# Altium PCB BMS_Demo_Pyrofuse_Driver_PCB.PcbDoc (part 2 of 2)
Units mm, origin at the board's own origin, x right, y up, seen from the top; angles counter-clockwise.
Board outline 130 x 44 mm, 2 copper layers (Top Layer, Bottom Layer), stack 1.575 mm thick; 66 components, 31 nets, 200 pads, 139 vias.
Unrouted connection lines stored in the file: 5.
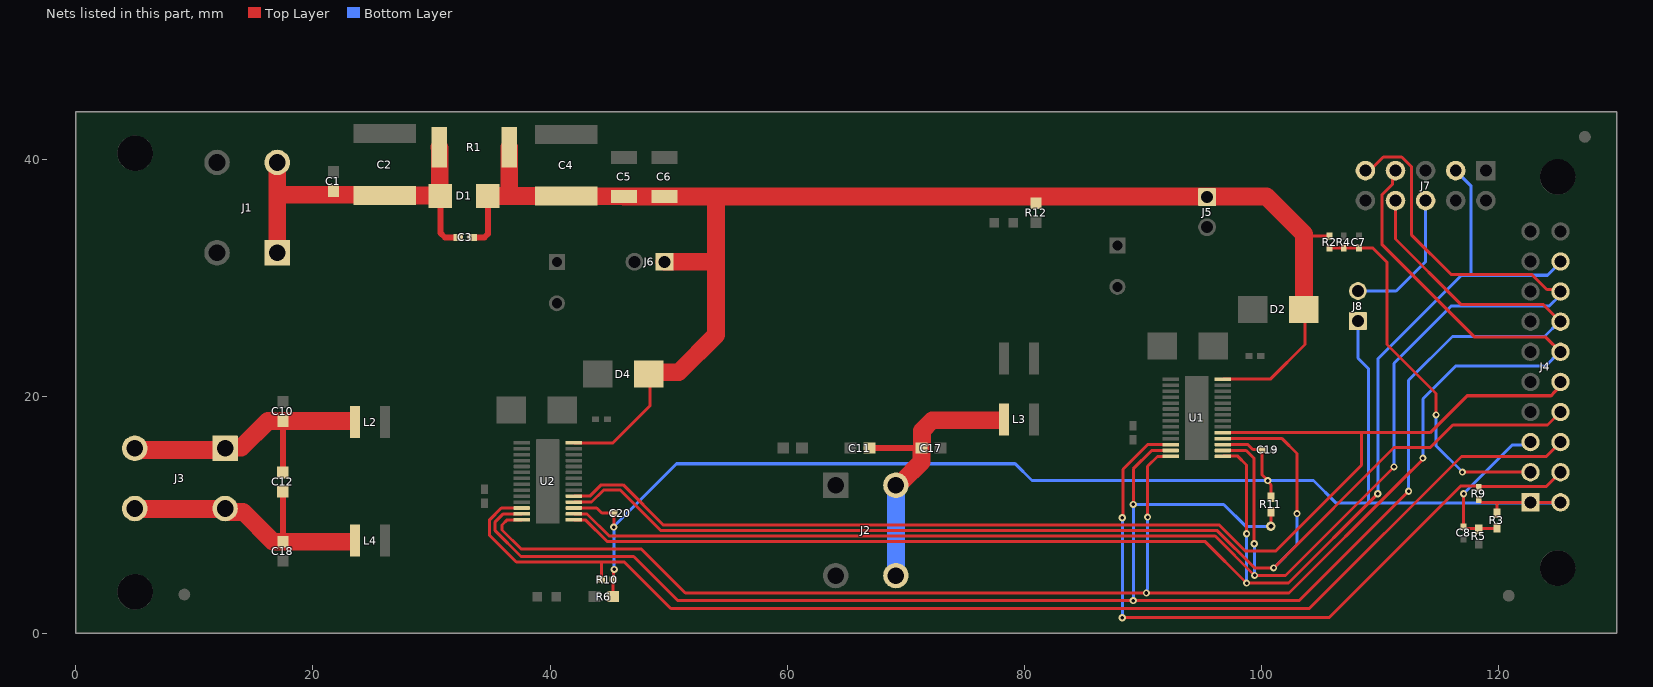
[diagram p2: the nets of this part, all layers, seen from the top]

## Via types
v1: diameter 0.8, hole 0.4, Top Layer to Bottom Layer, 71 vias
v2: diameter 0.61, hole 0.3, Top Layer to Bottom Layer, 40 vias
v3: diameter 0.5, hole 0.2, Top Layer to Bottom Layer, tented both sides, 28 vias

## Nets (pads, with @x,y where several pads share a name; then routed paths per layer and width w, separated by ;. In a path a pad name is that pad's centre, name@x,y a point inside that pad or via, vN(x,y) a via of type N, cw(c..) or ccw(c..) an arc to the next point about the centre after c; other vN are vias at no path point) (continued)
Pyro1-: C11.2 C17.1 J2.2 L3.2 | length 24.9
  Top Layer w0.5: C11.2@67.021,15.628 C17.1@71.346,15.628
  Top Layer w1.5: J2.2@68.96,12.24 68.96,12.273 J2.2@69.177,12.49 69.427,12.74 69.635,12.74 71.346,14.451 C17.1@71.346,15.628 71.371,15.653 71.371,17.098 72.249,17.977 L3.2@77.963,17.977
  Bottom Layer w1.5: J2.2@69.177,4.87 J2.2@69.177,12.49
Pyro2+: C10.1 C12.1 J3.1 L2.2 | length 23.6
  Top Layer w0.5: C12.1@17.462,13.575 C10.1@17.462,17.825 ; C10.1@17.462,17.825 C10.1@17.463,17.917
  Top Layer w1.5: J3.1@4.994,15.479 5.529,15.479 5.54,15.469 12.458,15.469 12.565,15.575 12.835,15.575 12.931,15.671 13.951,15.671 16.198,17.917 C10.1@17.463,17.917 17.766,17.917 17.775,17.909 L2.2@23.213,17.909
Pyro2-: C12.2 C18.1 J3.2 L4.2 | length 23.8
  Top Layer w0.5: C18.1@17.462,7.726 17.462,7.825 C12.2@17.462,11.974
  Top Layer w1.5: J3.2@4.856,10.495 12.7,10.495 12.95,10.245 14.109,10.245 16.629,7.725 C18.1@17.463,7.725 17.47,7.718 L4.2@23.213,7.718
PYRO_IO0: J4.4 R9.1 U1.26 | length 59.5
  Top Layer w0.254: v2(88.275,1.321) 105.714,1.321 116.804,12.411 118.34,12.411 118.351,12.4 124.06,12.4 J4.4@125.25,13.59 ; v2(88.275,9.757) 88.334,9.816 88.334,13.839 90.42,15.925 U1.26@92.363,15.925
  Bottom Layer w0.254: v2(88.275,1.321) v2(88.275,9.757)
PYRO_IO1: J4.6 R10.1 U2.26 | length 104.7
  Top Layer w0.254: U2.26@37.613,10.575 37.609,10.571 35.894,10.571 34.873,9.55 34.873,8.299 37.151,6.021 44.33,6.021 ; R10.1@44.33,4.529 44.33,6.021 ; J4.6@125.25,16.13 124.045,14.925 116.885,14.925 104.06,2.1 50.192,2.1 46.271,6.021 44.33,6.021
PYRO_IO2: J4.8 U1.4 U2.4 | length 109.1
  Top Layer w0.254: U2.4@42.013,11.075 43.501,11.075 44.501,12.075 45.95,12.075 49.36,8.665 96.299,8.665 99.447,5.518 v2(101.043,5.518) 111.201,15.675 114.267,15.675 116.16,17.568 124.148,17.568 J4.8@125.25,18.67 ; U1.4@96.763,16.425 101.768,16.425 103.016,15.177 v2(103.016,10.099)
  Bottom Layer w0.254: v2(101.043,5.518) 103.016,7.49 v2(103.016,10.099)
PYRO_IO3: J4.10 U1.5 U2.5 | length 105.4
  Top Layer w0.254: U2.5@42.013,11.575 43.359,11.575 44.313,12.529 46.168,12.529 49.578,9.119 96.487,9.119 98.677,6.929 101.199,6.929 108.453,14.184 108.453,16.925 ; U1.5@96.763,16.925 108.453,16.925 ; J4.10@125.25,21.21 125.25,20.859 124.643,20.252 124.643,20.226 124.46,20.043 117.369,20.043 114.252,16.925 108.453,16.925
PYRO_OPT_AN0: C7.1 J4.3 R2.1 R4.2 | length 31.4
  Top Layer w0.254: R2.1@105.768,32.495 R4.2@106.962,32.495 C7.1@108.232,32.495 109.433,32.495 110.617,31.31 110.617,24.359 114.749,20.226 v2(114.749,18.425) ; v2(116.972,13.602) 116.978,13.596 122.704,13.596 J4.3@122.71,13.59
  Bottom Layer w0.254: v2(114.749,18.425) 114.749,15.825 v2(116.972,13.602)
PYRO_OPT_AN1: C8.1 J4.5 R3.1 R5.2 | length 12.9
  Top Layer w0.254: v2(117.066,11.779) C8.1@117.066,8.974 117.182,8.858 118.267,8.858 R5.2@118.351,8.774 ; R5.2@118.351,8.847 R3.1@119.676,8.847
  Bottom Layer w0.254: v2(117.066,11.779) 121.169,15.882 122.462,15.882 J4.5@122.71,16.13
PYRO_SPI_CS: J4.16 J7.9 U1.2 U2.2 | length 138.4
  Top Layer w0.254: U2.2@42.013,10.075 43.122,10.075 44.986,8.211 96.111,8.211 v2(99.437,4.886) 102.047,4.886 v2(111.201,14.04) ; U1.2@96.763,15.425 98.725,15.425 99.407,14.742 v2(99.407,7.561) ; J7.9@108.788,39.04 109.144,39.04 110.296,40.192 111.844,40.192 112.657,39.379 112.657,33.632 116.021,30.268 122.83,30.268 124.094,29.004 125.076,29.004 J4.16@125.25,28.83
  Bottom Layer w0.254: v2(99.407,7.561) 99.422,7.546 99.422,4.9 v2(99.437,4.886) ; v2(111.201,14.04) 111.201,22.783 116.026,27.608 124.307,27.608 125.25,28.551 J4.16@125.25,28.83
PYRO_SPI_MISO: J4.14 J7.8 R11.1 U1.27 U2.27 | length 159.4
  Top Layer w0.254: U2.27@37.613,10.075 37.59,10.052 36.017,10.052 35.375,9.41 35.375,8.659 37.559,6.475 47.054,6.475 50.765,2.764 103.212,2.764 v2(112.431,11.984) ; v2(89.205,10.876) 89.205,13.873 90.756,15.425 U1.27@92.363,15.425 ; v1(100.813,9.024) R11.1@100.813,10.276 ; J7.8@111.328,36.5 111.328,33.274 116.874,27.728 123.812,27.728 J4.14@125.25,26.29
  Bottom Layer w0.254: v2(89.205,2.764) v2(89.205,10.876) 96.83,10.876 98.682,9.024 v1(100.813,9.024) ; v2(112.431,11.984) 112.431,21.341 116.135,25.044 123.887,25.044 125.133,26.29 J4.14@125.25,26.29
PYRO_SPI_MOSI: J4.12 J7.7 U1.28 U2.28 | length 143.7
  Top Layer w0.254: U2.28@37.613,9.575 36.382,9.575 35.95,9.143 35.95,8.726 37.567,7.108 47.703,7.108 51.411,3.4 v2(90.313,3.4) 102.348,3.4 111.809,12.861 113.638,14.69 v2(113.638,14.783) ; v2(90.413,9.803) 90.413,14.09 91.249,14.925 U1.28@92.363,14.925 ; J7.7@111.328,39.04 111.061,38.773 111.061,37.862 110.176,36.977 110.176,32.817 118.005,24.989 124.011,24.989 J4.12@125.25,23.75
  Bottom Layer w0.254: v2(90.313,3.4) 90.381,3.468 90.381,3.695 90.413,3.727 v2(90.413,9.803) ; v2(113.638,14.783) 113.638,19.788 116.39,22.539 123.981,22.539 125.191,23.75 J4.12@125.25,23.75
PYRO_SPI_SCK: J4.18 J7.3 U1.1 U2.1 | length 125
  Top Layer w0.254: U2.1@42.013,9.575 42.98,9.575 44.798,7.757 95.244,7.757 v2(98.762,4.238) 102.293,4.238 v2(109.834,11.779) ; U1.1@96.763,14.925 96.786,14.947 98.021,14.947 98.762,14.206 v2(98.762,8.392)
  Bottom Layer w0.254: v2(98.762,4.238) v2(98.762,8.392) ; v2(109.834,11.779) 109.834,23.143 116.899,30.208 117.678,30.208 ; J7.3@116.408,39.04 117.678,37.77 117.678,30.208 ; J4.18@125.25,31.37 125.25,31.31 124.148,30.208 117.678,30.208
VBAT: C3.1 C4.1 C5.1 C6.1 D1.1 D2.2 D4.2 J5.1 J6.1 R1.2 R2.2 R12.2 U1.14 U2.14 | length 132.1
  Top Layer w0.254: U2.14@42.013,16.075 45.316,16.075 48.453,19.212 D4.2@48.453,21.718 ; D4.2@47.443,21.874 D4.2@47.766,21.551 ; U1.14@96.763,21.425 96.782,21.444 100.769,21.444 103.694,24.37 103.694,27.22 D2.2@103.593,27.321 ; 103.728,33.92 104.137,33.511 R2.2@105.768,33.511
  Top Layer w0.5: C3.1@33.45,33.4 34.457,33.4 34.75,33.693 D1.1@34.75,36.9
  Top Layer w1.5: D1.1@34.75,36.9 36.619,36.9 ; R1.2@36.55,41.005 36.55,36.969 36.619,36.9 ; C5.1@46.25,36.85 C6.1@49.65,36.85 54,36.85 ; C5.1@46.25,36.875 41.388,36.875 C4.1@41.363,36.9 36.619,36.9 ; D4.2@48.574,22.031 50.863,22.031 54,25.167 54,31.344 ; J6.1@49.657,31.344 54,31.344 ; D2.2@103.593,27.321 103.609,27.336 103.609,33.683 100.442,36.85 95.428,36.85 83.713,36.85 70.719,36.85 54,36.85 ; 54,31.344 54,36.85
VBATI: C1.1 C2.1 C3.2 D1.2 J1.1 R1.1 | length 30.3
  Top Layer w0.5: D1.2@30.75,36.9 30.75,33.787 31.137,33.4 C3.2@32.25,33.4
  Top Layer w1.5: J1.1@16.987,31.893 16.987,37 ; J1.1@16.987,39.513 16.987,37 ; R1.1@30.65,41.005 30.7,40.955 30.7,36.95 D1.2@30.725,36.925 ; D1.2@30.75,36.9 D1.2@30.725,36.925 ; 16.987,37 26,37 C2.1@26.05,36.95 26.075,36.925 D1.2@30.725,36.925
VDD_USB2ANY: J7.6 J8.2 | length 11.9
  Bottom Layer w0.254: J8.2@108.153,28.878 111.378,28.878 113.868,31.369 J7.6@113.868,36.5
VDDIO: C19.2 C20.2 J4.1 J4.2 J8.1 R3.2 R6.2 R9.2 R10.2 R11.2 U1.3 U2.3 | length 125.7
  Top Layer w0.254: U2.3@42.013,10.575 43.935,10.575 44.363,10.146 C20.2@45.41,10.146 45.392,10.128 45.392,8.982 v2(45.374,8.964) ; R6.2@45.339,3.099 45.33,3.107 R10.2@45.33,4.529 45.37,4.569 45.37,5.349 v2(45.411,5.389) ; U1.3@96.763,15.925 98.867,15.925 99.293,15.499 C19.2@100.013,15.499 ; C19.2@100.043,15.481 100.051,15.473 100.051,13.392 v2(100.558,12.885) 100.558,12.789 100.813,12.534 R11.2@100.813,11.476 R11.2@100.813,11.426 ; R9.2@118.351,11.279 118.351,11.229 118.474,11.106 118.524,11.106 118.58,11.05 119.888,11.05 ; R3.2@119.888,10.125 119.888,11.05 ; J4.2@125.25,11.05 J4.1@122.71,11.05 119.888,11.05
  Bottom Layer w0.254: v2(45.411,5.389) 45.392,5.407 45.392,8.946 v2(45.374,8.964) 45.374,9.008 50.673,14.306 79.242,14.306 80.663,12.885 v2(100.558,12.885) 104.408,12.885 106.318,10.975 109.03,10.975 ; J8.1@108.153,26.338 108.153,23.212 109.03,22.335 109.03,10.975 ; J4.2@125.25,11.05 125.175,10.975 109.03,10.975
pads on no net: FID1.1 FID2.1 FID3.1 J4.7 J4.9 J4.11 J4.13 J4.15 J4.17 J7.1 J7.2 J7.4 J7.10 LBL1.0

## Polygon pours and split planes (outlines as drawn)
NetL1_1 on Top Layer "BOTTOM_LAYER_NONET_P-001" (solid, pour order 9): 93.013,20.049 93.013,19.3 88.334,19.3 83.222,21.825 80.838,21.825 80.838,24.525 85.553,24.525 90.029,20.049
NetL3_1 on Top Layer "BOTTOM_LAYER_NONET_P-001" (solid, pour order 10): 93.015,19.068 93.015,18.313 88.357,18.313 87.048,16.678 80.84,16.707 80.84,19.39 84.216,19.396 87.627,19.038
GND on Top Layer "BOTTOM_LAYER_NONET_P-001" (solid, remove dead copper, pour order 16): 0,44 0,0 130,0 130,44
NetL3_1 on Top Layer "BOTTOM_LAYER_NONET_P-001" (solid, pour order 15): 99.814,19.051 99.814,18.292 96.215,18.285 96.215,19.045
NetL1_1 on Top Layer "BOTTOM_LAYER_NONET_P-001" (solid, pour order 14): 99.417,20.043 99.417,19.301 96.206,19.295 96.206,20.038
NetC15_1 on Top Layer "BOTTOM_LAYER_NONET_P-001" (solid, pour order 13): 99.043,21.049 99.043,20.307 96.263,20.302 96.263,21.045
NetC13_1 on Top Layer "BOTTOM_LAYER_NONET_P-001" (solid, pour order 12): 90.414,31.421 86.413,31.421 86.413,34.265 92.888,34.265 92.888,21.276 90.414,21.276
NetC15_1 on Top Layer "BOTTOM_LAYER_NONET_P-001" (solid, pour order 11): 93.025,21.068 93.025,20.279 90.143,20.274 90.143,21.063
VBAT on Top Layer "BOTTOM_LAYER_NONET_P-001" (solid, pour order 8): 96.113,21.288 96.113,22.707 101.268,22.707 103.05,24.489 103.05,26.821 104.597,26.821 104.597,23.79 102.096,21.288
VBAT on Top Layer "BOTTOM_LAYER_NONET_P-001" (solid, pour order 7): 41.363,15.952 41.363,17.26 45.555,17.26 47.766,19.471 47.766,21.529 49.225,21.529 49.225,18.988 46.189,15.952
NetL4_1 on Top Layer "BOTTOM_LAYER_NONET_P-001" (solid, pour order 6): 45.18,13.707 45.18,12.948 41.372,12.941 41.372,13.701
NetL2_1 on Top Layer "BOTTOM_LAYER_NONET_P-001" (solid, pour order 5): 44.538,14.699 44.538,13.957 41.363,13.951 41.363,14.694
NetC16_1 on Top Layer "BOTTOM_LAYER_NONET_P-001" (solid, pour order 4): 44.128,15.705 44.128,14.963 41.421,14.958 41.421,15.701
NetC14_1 on Top Layer "BOTTOM_LAYER_NONET_P-001" (solid, pour order 3): 35.545,32.845 41.863,32.845 41.863,29.814 37.861,29.814 37.861,15.922 35.545,15.922
NetC16_1 on Top Layer "BOTTOM_LAYER_NONET_P-001" (solid, pour order 2): 38.252,15.705 38.252,14.916 35.545,14.912 35.545,15.701
NetL4_1 on Top Layer "BOTTOM_LAYER_NONET_P-001" (solid, pour order 1): 38.263,13.725 38.263,12.94 33.863,12.94 33.128,9.773 30.095,6.475 26.091,6.475 26.091,9.175 28.968,9.175 32.3,12.507 33.519,13.726
NetL2_1 on Top Layer "BOTTOM_LAYER_NONET_P-001" (solid, pour order 0): 38.263,14.705 38.263,13.942 33.52,13.942 28.518,16.475 26.088,16.475 26.088,19.175 30.654,19.175 35.124,14.705
GND on Bottom Layer "BOTTOM_LAYER_NONET_P-001" (solid, remove dead copper, pour order 17): 0,44 0,0 130,0 130,44

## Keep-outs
Keep-Out Layer:
  text ".Layer_Name" at 14.656,-21.806 h1.52

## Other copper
Top Layer:
  text ".Layer_Name" at 14.656,-21.806 h1.52
Bottom Layer:
  text ".Layer_Name" at 14.656,-21.806 h1.52

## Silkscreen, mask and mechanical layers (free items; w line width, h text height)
Top Overlay:
  text "'.PRJ_Number'.PCB_Rev" at 86.104,41.148 h2.75
  text "TI BMS DEMO - PYROFUSE DRIVER" at 51.98,38.408 h1.52
  text "USB2ANY" at 114.749,34.617 h1
  text "VBAT" at 76.889,32.831 h1
  text "GND" at 4.039,32.605 h1.52
  text "VBATI" at 20.692,32.315 h1.52
  text "Pyro2+" at 10.737,20.031 h1.52
  text "Pyrofuse Driver-DRV3901-Q1" at 81.813,12.631 h1.52
  text "Pyro1+" at 54.987,8.111 h1.52
  text "Pyro1-" at 74.643,8.043 h1.52
  text "Pyrofuse Driver-DRV3901-Q1" at 30.937,6.281 h1.52
  text "Pyro2-" at 10.737,4.519 h1.52
  text "VDDIO" at 38.169,1.048 h1
  text ".Layer_Name" at 14.656,-21.806 h1.52
Bottom Overlay:
  text ".Layer_Name" at 14.656,-21.806 h1.52
Top Paste:
  text ".Layer_Name" at 14.656,-21.806 h1.52
Bottom Paste:
  text ".Layer_Name" at 14.656,-21.806 h1.52
Top Solder:
  text ".Layer_Name" at 14.656,-21.806 h1.52
  text ".Layer_Name" at 14.656,-21.806 h1.52
Bottom Solder:
  text ".Layer_Name" at 14.656,-21.806 h1.52
Drill Guide:
  text ".Layer_Name" at 14.656,-21.806 h1.52
M1 Board Outline:
  the board outline again, w0.254
  text ".Layer_Name" at 14.656,-21.806 h1.52
M2 Board Dimensions:
  rectangle: 3.175,-10.16 12.7,-6.985
  rectangle: 0,-6.985 3.175,-3.81
  lines w0.178: 0,-6.985 25.4,-6.985 ; 3.175,-10.16 3.175,-3.81 ; 6.35,-10.16 6.35,-3.81 ; 12.7,-10.16 12.7,-3.81 ; 19.05,-10.16 19.05,-3.81 ; 0,-10.16 0,-3.81 25.4,-3.81 25.4,-10.16 0,-10.16
  text ".Layer_Name" at 14.656,-21.806 h1.52
M3 3D STEP Top:
  text ".Layer_Name" at 14.656,-21.806 h1.52
M4 3D STEP Bottom:
  text ".Layer_Name" at 14.656,-21.806 h1.52
M5 Assembly Top:
  lines w0.254: -7.417,-23.626 160.223,-23.626 ; -7.417,-18.462 160.274,-18.462 ; -7.417,-13.297 -7.417,-28.791 94.31,-28.791 160.274,-28.791 160.274,-13.297 -7.404,-13.297 -7.404,-28.791 32.614,-28.791 ; 55.194,-28.791 55.194,-13.297 ; 87.376,-18.462 87.376,-13.297 ; 108.712,-18.462 108.712,-13.297 ; 124.511,-28.956 124.511,-23.804
  text "COMPONENTS MARKED 'DNP' SHOULD NOT BE POPULATED." at 29.299,-8.09 h1.52
  text "ASSEMBLY VARIANT:" at 29.286,-11.024 h1.52
  text ".VariantName" at 55.601,-11.024 h1.52
  text "PCB VIEWED FROM TOP SIDE" at -5.804,-16.654 h1.52
  text "BOARD #:" at 57.099,-16.654 h1.52
  text ".PRJ_Number" at 70.955,-16.654 h1.52
  text "REV:" at 92.405,-16.654 h1.52
  text ".PCB_Rev" at 99.809,-16.654 h1.52
  text "SVN REV:" at 113.69,-16.654 h1.52
  text ".VersionControl_RevNumber" at 126.543,-16.654 h1.52
  text "PLOT NAME =" at -5.804,-27.034 h1.52
  text ".plot_File_Name" at 14.656,-27.034 h1.52
  text "GENERATED    :" at 57.15,-27.034 h1.52
  text ".Print_Date" at 79.235,-27.034 h1.52
  text ".Print_Time" at 97.752,-27.034 h1.52
  text "TEXAS INSTRUMENTS" at 129.87,-27.034 h1.52
M6 Assembly Bottom:
  lines w0.254: -7.429,-18.474 160.261,-18.474 ; -7.379,-23.639 160.261,-23.639 ; 28.334,-28.969 28.334,-23.817 ; 44.133,-18.474 44.133,-13.31 ; 65.468,-18.474 65.468,-13.31 ; 97.65,-28.804 97.65,-13.31 ; 120.231,-28.804 160.249,-28.804 160.249,-13.31 -7.429,-13.31 -7.429,-28.804 58.534,-28.804 160.261,-28.804 160.261,-13.31
  text "COMPONENTS MARKED 'DNP' SHOULD NOT BE POPULATED." at 154.991,-8.077 h1.52
  text ".VariantName" at 128.473,-11.024 h1.52
  text "ASSEMBLY VARIANT:" at 154.864,-11.024 h1.52
  text ".VersionControl_RevNumber" at 26.302,-16.667 h1.52
  text "SVN REV:" at 39.154,-16.667 h1.52
  text ".PCB_Rev" at 53.035,-16.667 h1.52
  text "REV:" at 60.439,-16.667 h1.52
  text ".PRJ_Number" at 81.89,-16.667 h1.52
  text "BOARD #:" at 95.745,-16.667 h1.52
  text "PCB VIEWED FROM BOTTOM SIDE" at 158.648,-16.667 h1.52
  text "TEXAS INSTRUMENTS" at 22.974,-27.047 h1.52
  text ".Print_Time" at 55.093,-27.047 h1.52
  text ".Print_Date" at 73.609,-27.047 h1.52
  text "GENERATED    :" at 95.694,-27.047 h1.52
  text ".plot_File_Name" at 138.189,-27.047 h1.52
  text "PLOT NAME =" at 158.648,-27.047 h1.52
M9 Title Sheet:
  drawing of 56 lines, arcs and shapes, not listed
  text "1" at 26.882,339.887 h1.78
  text "2" at 111.354,339.887 h1.78
  text "3" at 195.936,339.887 h1.78
  text "4" at 280.645,339.887 h1.78
  text "5" at 365.1,339.887 h1.78
  text "6" at 449.809,339.887 h1.78
  text "A" at -11.76,294.726 h1.78
  text "A" at 488.62,294.726 h1.78
  text "B" at -11.76,199.476 h1.78
  text "B" at 488.62,199.476 h1.78
  text "C" at -11.76,104.226 h1.78
  text "C" at 488.62,104.226 h1.78
  text "D" at -11.76,8.976 h1.78
  text "D" at 488.62,8.976 h1.78
  text "PROJECT TITLE:" at 410.032,6.817 h1.14
  text ".PRJ_Title" at 411.302,3.431 h1.78
  text "DESIGNED FOR:" at 410.032,-0.828 h1.14
  text ".PRJ_Customer" at 411.302,-4.384 h1.78
  text "FILE NAME:" at 410.032,-8.448 h1.14
  text ".PCB_File_Name_No_Path" at 411.302,-11.496 h1.78
  text "Texas Instruments (TI) and/or its licensors do not warrant the accuracy or completeness of this specification" at 283.807,-15.607 h1.14
  text "ENGINEER:" at 410.032,-15.814 h1.14
  text "LAYOUT BY:" at 448.259,-15.814 h1.14
  text "or any information contained therein. TI and/or its licensors do not warrant that this design will meet" at 282.664,-18.469 h1.14
  text ".PRJ_Engineer" at 411.302,-19.751 h1.78
  text ".PCB_Layout" at 449.542,-19.751 h1.78
  text "the specifications, will be suitable for your application or fit for any particular purpose, or will operate in" at 282.664,-21.33 h1.14
  text ".Layer_Name" at 14.656,-21.806 h1.52
  text "ALTIUM DESIGNER VERSION:" at 448.259,-23.688 h1.14
  text "an implementation. TI and/or its licensors do not warrant that the design is production worthy. You should" at 282.664,-24.192 h1.14
  text "completely validate and test your design implementation to confirm the system functionality for your application." at 283.807,-27.054 h1.14
  text ".print_Scale" at 411.302,-27.075 h1.78
  text ".Application_BuildNumber" at 449.542,-27.075 h1.78
  text "1" at 26.882,-33.493 h1.78
  text "2" at 111.354,-33.493 h1.78
  text "3" at 195.936,-33.493 h1.78
  text "4" at 280.645,-33.493 h1.78
  text "5" at 365.1,-33.493 h1.78
  text "6" at 449.809,-33.493 h1.78
M10 Fab Notes:
  drawing of 189 lines, arcs and shapes, not listed
  text "DESIGN INFORMATION" at 436.322,161.675 h1.52
  text "MIN. TRACK WIDTH:" at 419.95,158.319 h1.52
  text "8" at 447.794,158.32 h1.52
  text "MIL" at 451.725,158.319 h1.52
  text "MIN. CLEARANCE:" at 419.95,155.167 h1.52
  text "MIL" at 451.725,155.167 h1.52
  text "7.874" at 443.475,155.05 h1.52
  text "MIN. VIA PAD SIZE:" at 419.95,152.014 h1.52
  text "24" at 447.033,152.014 h1.52
  text "MIL" at 451.725,152.014 h1.52
  text "0.05mm (2MIL)" at 437.603,148.714 h1.52
  text "MINIMUM ANNULAR RING" at 411.587,148.506 h1.52
  text "EXTERNAL" at 455.586,148.506 h1.52
  text "PER" at 416.667,145.708 h1.52
  text "IPC-D-275 CLASS 2 LEVEL C" at 422.255,145.708 h1.52
  text "MIL, HOLES" at 460.056,143.156 h1.52
  text "+/-" at 450.088,142.938 h1.52
  text "+/-" at 471.78,142.938 h1.52
  text "REGISTRATION TOLERANCES:" at 411.587,142.911 h1.52
  text "METAL" at 442.062,142.911 h1.52
  text "5" at 456.697,142.911 h1.52
  text "3" at 477.855,142.911 h1.52
  text "MIL" at 480.808,142.911 h1.52
  text "HOLE SIZE TOLERANCE (UNLESS OTHERWISE SPECIFIED):" at 411.587,140.414 h1.52
  text "+/-" at 471.78,140.341 h1.52
  text "3" at 477.855,140.314 h1.52
  text "MIL" at 480.808,140.314 h1.52
  text "MATERIAL:" at 409.688,136.818 h1.52
  text "FR-4 High Tg" at 434.744,133.553 h1.52
  text "X" at 431.075,133.35 h1.52
  text "FR-408" at 420.382,133.235 h1.52
  text "OTHER" at 458.177,133.235 h1.52
  text "62 MIL (1.6mm) +/-10%" at 428.512,129.602 h1.52
  text "X" at 425.462,129.54 h1.52
  text "THICKNESS:" at 411.587,129.394 h1.52
  text "OTHER" at 461.149,129.394 h1.52
  text "TOLERANCE:" at 411.587,125.88 h1.52
  text "X" at 433.133,125.88 h1.52
  text "ANSI IPC-6012 TYPE 3 CLASS 2" at 437.654,125.88 h1.52
  text "OTHER +/-" at 437.654,122.218 h1.52
  text "BOW & TWIST:" at 411.587,118.53 h1.52
  text "X" at 433.133,118.53 h1.52
  text "ANSI IPC-6012 TYPE 3 CLASS 2" at 437.654,118.53 h1.52
  text "OTHER +/-" at 437.654,114.804 h1.52
  text "DRILLING:" at 409.688,111.486 h1.52
  text "NC_DRILL FILES" at 454.418,108.815 h1.52
  text "REFERENCE:" at 411.587,108.715 h1.52
  text "X" at 428.281,108.712 h1.52
  text "AS SHOWN" at 432.802,108.715 h1.52
  text "X" at 451.167,108.715 h1.52
  text "OTHER" at 461.987,105.101 h1.52
  text "PTH COPPER THICKNESS:" at 411.579,105.012 h1.52
  text "X" at 440.516,105.012 h1.52
  text "20-30 um" at 443.767,105.012 h1.52
  text "BOARD FINISH:" at 409.688,101.263 h1.52
  text "SILKSCREEN:" at 413.631,98.466 h1.52
  text "X" at 437.959,98.466 h1.52
  text "TOP" at 440.93,98.466 h1.52
  text "X" at 450.913,98.466 h1.52
  text "BOTTOM" at 453.91,98.466 h1.52
  text "SILKSCREEN COLOR:" at 413.631,94.524 h1.52
  text "X" at 437.933,94.524 h1.52
  text "WHITE" at 440.93,94.524 h1.52
  text "OTHER" at 453.91,94.524 h1.52
  text "X" at 441.261,90.88 h1.52
  text "GREEN" at 444.258,90.88 h1.52
  text "OTHER" at 459.955,90.88 h1.52
  text "SOLDER RESIST COLOR:" at 413.631,90.706 h1.52
  text "X" at 441.261,86.962 h1.52
  text "MATTE" at 444.258,86.962 h1.52
  text "SEMI-GLOSS" at 459.943,86.946 h1.52
  text "IMMERSION GOLD (ENIG)" at 436.638,82.574 h1.52
  text "ENEPIG" at 470.611,82.39 h1.52
  text "SURFACE FINISH:" at 409.688,82.365 h1.52
  text "X" at 432.117,82.365 h1.52
  text "IMM. TIN/SILVER OR EQUIV" at 418.059,78.877 h1.52
  text "OTHER" at 454.418,78.777 h1.52
  text "ARRAY/PANEL:" at 409.688,74.831 h1.52
  text "CUT AND TRIM PER M1 BOARD OUTLINE" at 436.638,74.622 h1.52
  text "N.C. ROUTE" at 436.638,71.168 h1.52
  text "X" at 454.113,71.168 h1.52
  text "V. SCORE" at 458.634,71.168 h1.52
  text "CERTIFICATION:" at 409.688,67.888 h1.52
  text "MATERIALS AND WORKMANSHIP FOR ALL PCBS" at 428.103,67.888 h1.52
  text "TO MEET OR EXCEED THE REQUIREMENTS OF:" at 428.103,65.499 h1.52
  text "X" at 418.896,62.232 h1.52
  text "ANSI IPC-A-600F CLASS ->" at 422.147,62.232 h1.52
  text "X" at 464.006,62.232 h1.52
  text "2" at 466.8,62.232 h1.52
  text "1" at 458.799,62.194 h1.52
  text "3" at 475.792,62.194 h1.52
  text "X" at 439.521,58.481 h1.52
  text "RoHS" at 442.772,58.481 h1.52
  text "OTHER" at 459.14,58.481 h1.52
  text "PER ORDER" at 469.225,58.481 h1.52
  text "ALL BOARDS MUST MEET OR EXCEED UL94-V0 REQUIREMENTS." at 410.388,54.574 h1.52
  text "PCB MUST BEAR THE UL94V-0 UL REGISTERED MATERIAL ID NUMBER" at 410.388,51.626 h1.52
  text "ADDITIONAL REQUIREMENTS:" at 409.688,47.322 h1.52
  text "MICROSECTION:" at 411.587,44.601 h1.52
  text "YES" at 434.593,44.601 h1.52
  text "REQUIRED" at 456.475,40.935 h1.52
  text "BARE BOARD ELEC. TEST:" at 411.587,40.863 h1.52
  text "NONE" at 444.753,40.863 h1.52
  text "X" at 453.478,40.863 h1.52
  text "PER ORDER" at 471.512,40.863 h1.52
  text "XX MIL VIAS REQUIRE NON-CONDUCTIVE FILL AND PLANARIZE" at 415.858,35.657 h1.5
  text "XX MIL VIAS REQUIRE CONDUCTIVE FILL AND PLANARIZE" at 416.062,33.016 h1.52
  text "OUTER XX MIL TRACES REQUIRE 50 OHM SINGLE-ENDED IMPEDANCE" at 416.037,28.866 h1.47
  text "LAYER 2 & 3 (INNER LAYERS) XX MIL WIDE, XX MIL SPACE / TRACES REQUIRE 100 OHM DIFFERENTIAL IMPEDANCE" at 415.833,22.879 h1.52
  text ".Layer_Name" at 14.656,-21.806 h1.52
M11 Gerber Information:
  lines w0.254: -7.417,-23.626 160.223,-23.626 ; -7.417,-18.462 160.274,-18.462 ; -7.417,-13.297 -7.417,-28.791 94.31,-28.791 160.274,-28.791 160.274,-13.297 -7.404,-13.297 -7.404,-28.791 32.614,-28.791 ; 55.194,-28.791 55.194,-13.297 ; 87.376,-18.462 87.376,-13.297 ; 108.712,-18.462 108.712,-13.297 ; 124.511,-28.956 124.511,-23.804
  text "ALL ARTWORK VIEWED FROM TOP SIDE" at -5.804,-16.654 h1.52
  text "BOARD #:" at 57.099,-16.654 h1.52
  text ".PRJ_Number" at 70.955,-16.654 h1.52
  text "REV:" at 92.405,-16.654 h1.52
  text ".PCB_Rev" at 99.809,-16.654 h1.52
  text "SVN REV:" at 113.69,-16.654 h1.52
  text ".VersionControl_RevNumber" at 126.543,-16.654 h1.52
  text "LAYER NAME =" at -5.804,-21.806 h1.52
  text "PLOT NAME =" at -5.804,-27.034 h1.52
  text ".plot_File_Name" at 14.656,-27.034 h1.52
  text "GENERATED    :" at 57.15,-27.034 h1.52
  text ".Print_Date" at 79.235,-27.034 h1.52
  text ".Print_Time" at 97.752,-27.034 h1.52
  text "TEXAS INSTRUMENTS" at 129.87,-27.034 h1.52
M12 Stackup:
  drawing of 191 lines, arcs and shapes, not listed
  text "Layer" at 370.969,332.524 h1.52
  text "Name" at 381.38,332.524 h1.52
  text "Material" at 404.996,332.524 h1.52
  text "Thickness" at 426.834,332.524 h1.52
  text "Constant" at 443.34,332.524 h1.52
  text "Board Layer Stack" at 457.814,332.524 h1.52
  text "Top Overlay" at 381.38,329.476 h1.52
  text "Top Solder" at 381.38,326.428 h1.52
  text "Solder Resist" at 404.996,326.428 h1.52
  text "0.40mil" at 426.834,326.428 h1.52
  text "3.5" at 443.34,326.428 h1.52
  text "1" at 370.969,323.38 h1.52
  text "Top Layer" at 381.38,323.38 h1.52
  text "1.40mil" at 426.834,323.38 h1.52
  text "Dielectric1" at 381.38,320.332 h1.52
  text "FR-4 High Tg" at 404.996,320.332 h1.52
  text "59.20mil" at 426.834,320.332 h1.52
  text "4.8" at 443.34,320.332 h1.52
  text "2" at 370.969,317.284 h1.52
  text "Bottom Layer" at 381.38,317.284 h1.52
  text "1.40mil" at 426.834,317.284 h1.52
  text "Bottom Solder" at 381.38,314.236 h1.52
  text "Solder Resist" at 404.996,314.236 h1.52
  text "0.40mil" at 426.834,314.236 h1.52
  text "3.5" at 443.34,314.236 h1.52
  text "Bottom Overlay" at 381.38,311.188 h1.52
  text ".Layer_Name" at 14.656,-21.806 h1.52
M13 Component Bodies Top:
  text ".Layer_Name" at 14.656,-21.806 h1.52
M14 Component Bodies Bottom:
  text ".Layer_Name" at 14.656,-21.806 h1.52
M15 Courtyards Top:
  text ".Layer_Name" at 14.656,-21.806 h1.52
M16 Courtyards Bottom:
  text ".Layer_Name" at 14.656,-21.806 h1.52
Drill Drawing:
  circle w0.254: c138.27,80.263 r0.702
  circle w0.254: c138.27,61.317 r0.421
  circle w0.254: c138.27,61.317 r0.702
  lines w0.254: 137.569,57.457 138.972,57.457 138.972,58.861 137.569,58.861 137.569,57.457 ; 137.569,64.124 137.92,64.124 138.27,63.773 138.621,64.124 138.972,64.124 138.621,64.474 138.972,64.825 138.621,64.825 138.27,65.176 137.92,64.825 137.569,64.825 137.92,64.474 137.569,64.124 ; 137.569,67.632 138.27,66.93 138.972,67.632 138.27,68.334 137.569,67.632 ; 137.569,70.088 138.972,70.088 138.972,71.492 137.569,71.492 137.569,70.088 ; 137.569,73.246 138.27,73.597 138.972,73.246 138.621,73.948 138.972,74.649 138.27,74.298 137.569,74.649 137.92,73.948 137.569,73.246 ; 137.569,76.404 137.569,76.754 137.92,77.105 137.569,77.456 137.569,77.807 137.92,77.807 138.27,77.456 138.621,77.807 138.972,77.807 138.972,77.456 138.621,77.105 138.972,76.754 138.972,76.404 138.621,76.404 138.27,76.754 137.92,76.404 137.569,76.404 ; 137.569,83.07 137.92,83.07 137.92,82.719 138.621,82.719 138.621,83.07 138.972,83.07 138.972,83.772 138.621,83.772 138.621,84.122 137.92,84.122 137.92,83.772 137.569,83.772 137.569,83.07 ; 137.849,70.369 138.691,70.369 138.691,71.211 137.849,71.211 137.849,70.369
  lines w0.305: 136.296,56.51 218.376,56.51 ; 136.296,84.929 218.376,84.929 ; 144.878,53.352 144.878,88.087 ; 153.311,53.352 153.311,88.087 ; 169.48,53.352 169.48,88.087 ; 176.062,53.352 176.062,88.087 ; 185.591,53.352 185.591,88.087 ; 203.989,53.352 203.989,88.087 ; 136.296,53.352 218.376,53.352 218.376,88.087 136.296,88.087 136.296,53.352
  text "Symbol" at 138.191,85.877 h1.83
  text "Quantity" at 145.825,85.877 h1.83
  text "Finished Hole Size" at 154.258,85.877 h1.83
  text "Plated" at 170.427,85.877 h1.83
  text "Hole Type" at 177.009,85.877 h1.83
  text "Drill Layer Pair" at 186.538,85.877 h1.83
  text "Hole Tolerance" at 204.936,85.877 h1.83
  text "28" at 145.825,82.719 h1.52
  text "7.87mil (0.200mm)" at 154.258,82.719 h1.52
  text "PTH" at 170.427,82.719 h1.52
  text "Round" at 177.009,82.719 h1.52
  text "Top Layer - Bottom Layer" at 186.538,82.719 h1.52
  text "40" at 145.825,79.561 h1.52
  text "11.81mil (0.300mm)" at 154.258,79.561 h1.52
  text "PTH" at 170.427,79.561 h1.52
  text "Round" at 177.009,79.561 h1.52
  text "Top Layer - Bottom Layer" at 186.538,79.561 h1.52
  text "71" at 145.825,76.404 h1.52
  text "15.75mil (0.400mm)" at 154.258,76.404 h1.52
  text "PTH" at 170.427,76.404 h1.52
  text "Round" at 177.009,76.404 h1.52
  text "Top Layer - Bottom Layer" at 186.538,76.404 h1.52
  text "4" at 145.825,73.246 h1.52
  text "33.47mil (0.850mm)" at 154.258,73.246 h1.52
  text "PTH" at 170.427,73.246 h1.52
  text "Round" at 177.009,73.246 h1.52
  text "Top Layer - Bottom Layer" at 186.538,73.246 h1.52
  text "10" at 145.825,70.088 h1.52
  text "39.37mil (1.000mm)" at 154.258,70.088 h1.52
  text "PTH" at 170.427,70.088 h1.52
  text "Round" at 177.009,70.088 h1.52
  text "Top Layer - Bottom Layer" at 186.538,70.088 h1.52
  text "6" at 145.825,66.93 h1.52
  text "40.00mil (1.016mm)" at 154.258,66.93 h1.52
  text "PTH" at 170.427,66.93 h1.52
  text "Round" at 177.009,66.93 h1.52
  text "Top Layer - Bottom Layer" at 186.538,66.93 h1.52
  text "20" at 145.825,63.773 h1.52
  text "40.16mil (1.020mm)" at 154.258,63.773 h1.52
  text "PTH" at 170.427,63.773 h1.52
  text "Round" at 177.009,63.773 h1.52
  text "Top Layer - Bottom Layer" at 186.538,63.773 h1.52
  text "12" at 145.825,60.615 h1.52
  text "55.12mil (1.400mm)" at 154.258,60.615 h1.52
  text "PTH" at 170.427,60.615 h1.52
  text "Round" at 177.009,60.615 h1.52
  text "Top Layer - Bottom Layer" at 186.538,60.615 h1.52
  text "4" at 145.825,57.457 h1.52
  text "118.11mil (3.000mm)" at 154.258,57.457 h1.52
  text "PTH" at 170.427,57.457 h1.52
  text "Round" at 177.009,57.457 h1.52
  text "Top Layer - Bottom Layer" at 186.538,57.457 h1.52
  text "195 Total" at 145.825,54.3 h1.52
  text ".Layer_Name" at 14.656,-21.806 h1.52
M17 Embedded Cavity:
  text ".Layer_Name" at 14.656,-21.806 h1.52
M18 Embedded Assembly:
  text ".Layer_Name" at 14.656,-21.806 h1.52
M19 Embedded Keepout:
  text ".Layer_Name" at 14.402,-21.806 h1.52

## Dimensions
0,-10.16 to 25.4,-10.16 on M2 Board Dimensions
0,0 to 130,0 on M2 Board Dimensions
0,0 to 0,44 on M2 Board Dimensions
